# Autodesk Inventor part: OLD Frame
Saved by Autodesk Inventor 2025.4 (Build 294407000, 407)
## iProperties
Created: 2026-06
Part Number: OLD Frame
Material: Generic
Document SubType Name: Modeling
Designer: AdminForWorker
Density: 1 g/cm^3
Appearance: Default
Title: OLD Frame
Author: AdminForWorker
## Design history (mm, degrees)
